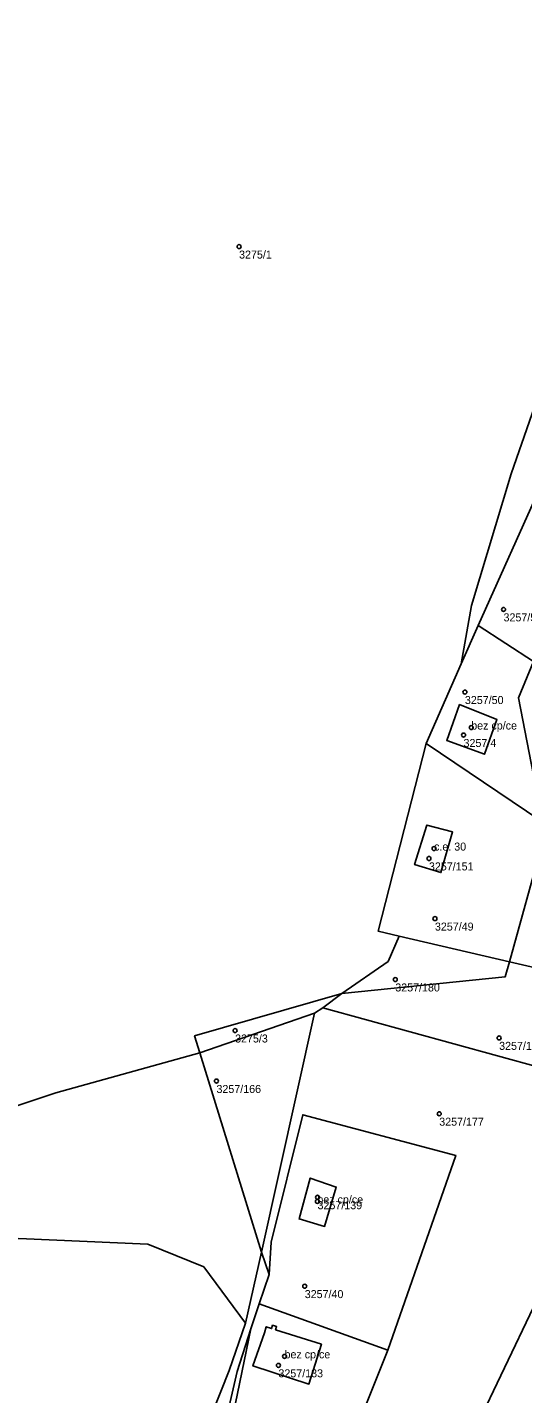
# Model space of a CAD drawing. Extents: x -878211 to -870363, y -1058464 to -1052522.
# Drawn here: x -876125.2 to -876063.3, y -1056729.3 to -1056558.5 of the extents above; entities that cross this region are included whole.
import ezdxf

# ---------------------------------------------------------------- set-up
doc = ezdxf.new("R2010")
doc.units = 0
for name, color, linetype in [('Vrstva 50', 7, 'Continuous'), ('Vrstva 51', 7, 'Continuous'), ('Vrstva 52', 7, 'Continuous')]:
    doc.layers.add(name, color=color, linetype=linetype)

msp = doc.modelspace()

# ---------------------------------------------------------------- linework, layer by layer
at = {"layer": 'Vrstva 50'}
for centre in [(-876098.72, -1056585.93994), (-876065.65, -1056631.28994), (-876070.48, -1056641.61994), (-876070.65, -1056646.98994), (-876069.69, -1056646.04994), (-876074.98, -1056662.41994), (-876074.34, -1056661.17994), (-876074.23, -1056669.93994), (-876079.19, -1056677.54994), (-876099.22, -1056683.92994), (-876066.2, -1056684.84994), (-876101.55, -1056690.23994), (-876073.69, -1056694.32994), (-876088.93, -1056705.28994), (-876088.91, -1056704.76994), (-876090.51, -1056715.87994), (-876093.8, -1056725.77994), (-876093.04, -1056724.64994)]:
    msp.add_circle(centre, 0.25, dxfattribs=at)
at = {"layer": 'Vrstva 51'}
for points in [[(-876148.16, -1056700.5), (-876121.62, -1056691.73), (-876103.64, -1056686.72), (-876104.28, -1056684.6), (-876085.87, -1056679.29), (-876080.06, -1056675.29), (-876078.71, -1056672.13), (-876081.31, -1056671.52), (-876075.34, -1056648.03), (-876070.94, -1056638.08), (-876069.67, -1056630.78), (-876064.71, -1056614.32), (-876056.8, -1056591.72), (-876042.56, -1056553.18), (-876035.37, -1056538.13), (-876027.85, -1056524.56), (-876017.07, -1056511.44), (-876044.68, -1056501.38), (-876098.73, -1056474.1), (-876103.25, -1056477.52), (-876108.02, -1056486.39), (-876113.38, -1056501.74), (-876122.52, -1056533.99), (-876125.96, -1056540.6)], [(-876042.56, -1056553.18), (-876056.8, -1056591.72), (-876064.71, -1056614.32), (-876069.67, -1056630.78), (-876070.94, -1056638.08), (-876068.81, -1056633.28), (-876060.76, -1056615.37), (-876053.64, -1056599.58), (-876052.39, -1056596.71), (-876049.88, -1056591.06), (-876048.41, -1056588.2), (-876043.14, -1056584.76), (-876040.29, -1056583.07), (-876043.26, -1056583.45), (-876046.42, -1056579.75), (-876036.33, -1056566.09), (-876027.33, -1056559.37), (-876025.32, -1056552.32)], [(-876057.84, -1056676.97), (-876064.92, -1056675.33), (-876065.44, -1056677.21), (-876085.87, -1056679.29), (-876088.26, -1056681.07), (-876055.5, -1056690.1)], [(-876030.88, -1056731.83), (-876010.97, -1056704.44), (-876010.13, -1056702.47), (-876055.5, -1056690.1), (-876088.26, -1056681.07), (-876089.29, -1056681.74), (-876095.92, -1056711.64), (-876094.94, -1056714.42), (-876094.69, -1056710.38), (-876090.76, -1056694.44), (-876071.62, -1056699.53), (-876080.1, -1056723.87), (-876085.64, -1056737.64)], [(-876069.17, -1056733.67), (-876061.91, -1056718.52), (-876055.49, -1056704.94), (-876049.98, -1056693.19), (-876021.18, -1056704.96), (-876020.86, -1056708.34), (-876027.78, -1056718.93), (-876035.95, -1056731.21)], [(-876108.71, -1056748.44), (-876099.97, -1056726.4), (-876097.92, -1056720.49), (-876103.15, -1056713.45), (-876110.12, -1056710.63), (-876126.27, -1056709.92), (-876142.37, -1056711.62), (-876162.32, -1056718.26), (-876174.86, -1056722.2), (-876191.58, -1056722.31), (-876199.78, -1056721.29), (-876212.54, -1056718.81), (-876216.57, -1056717.3), (-876255.67, -1056710.81), (-876298.64, -1056707.82), (-876323.97, -1056704.57), (-876331.67, -1056701.82), (-876328.4, -1056735.69)]]:
    msp.add_lwpolyline(points, dxfattribs=at)
for points in [[(-876068.81, -1056633.28), (-876061.89, -1056637.81), (-876059.31, -1056631.66), (-876051.13, -1056625.11), (-876039.66, -1056628.45), (-876060.76, -1056615.37)], [(-876075.34, -1056648.03), (-876060.98, -1056657.73), (-876061.1, -1056656.09), (-876063.79, -1056642.33), (-876061.89, -1056637.81), (-876068.81, -1056633.28), (-876070.94, -1056638.08)], [(-876043.28, -1056649.98), (-876061.89, -1056637.81), (-876063.79, -1056642.33), (-876061.1, -1056656.09), (-876060.98, -1056657.73), (-876051.83, -1056663.92)], [(-876066.47, -1056645.05), (-876068.03, -1056649.38), (-876072.76, -1056647.67), (-876071.14, -1056643.18)], [(-876066.47, -1056645.05), (-876071.14, -1056643.18), (-876072.76, -1056647.67), (-876068.03, -1056649.38)], [(-876060.98, -1056657.73), (-876075.34, -1056648.03), (-876081.31, -1056671.52), (-876078.71, -1056672.13), (-876064.92, -1056675.33), (-876060.79, -1056660.41)], [(-876073.47, -1056664.17), (-876076.78, -1056663.17), (-876075.26, -1056658.25), (-876072.03, -1056659.07)], [(-876073.47, -1056664.17), (-876072.03, -1056659.07), (-876075.26, -1056658.25), (-876076.78, -1056663.17)], [(-876060.98, -1056657.73), (-876060.79, -1056660.41), (-876064.92, -1056675.33), (-876057.84, -1056676.97), (-876051.83, -1056663.92)], [(-876064.92, -1056675.33), (-876078.71, -1056672.13), (-876080.06, -1056675.29), (-876085.87, -1056679.29), (-876065.44, -1056677.21)], [(-876088.26, -1056681.07), (-876085.87, -1056679.29), (-876104.28, -1056684.6), (-876103.64, -1056686.72), (-876089.29, -1056681.74)], [(-876089.29, -1056681.74), (-876103.64, -1056686.72), (-876095.92, -1056711.64)], [(-876121.62, -1056691.73), (-876148.16, -1056700.5), (-876153.47, -1056701.78), (-876173.86, -1056700.95), (-876176.72, -1056706.93), (-876187.92, -1056715.44), (-876216.57, -1056717.3), (-876212.54, -1056718.81), (-876199.78, -1056721.29), (-876191.58, -1056722.31), (-876174.86, -1056722.2), (-876162.32, -1056718.26), (-876142.37, -1056711.62), (-876126.27, -1056709.92), (-876110.12, -1056710.63), (-876103.15, -1056713.45), (-876097.92, -1056720.49), (-876095.92, -1056711.64), (-876103.64, -1056686.72)], [(-876080.1, -1056723.87), (-876071.62, -1056699.53), (-876090.76, -1056694.44), (-876094.69, -1056710.38), (-876094.94, -1056714.42), (-876096.19, -1056718.08)], [(-876088.03, -1056708.41), (-876091.22, -1056707.47), (-876089.83, -1056702.37), (-876086.58, -1056703.5)], [(-876088.03, -1056708.41), (-876086.58, -1056703.5), (-876089.83, -1056702.37), (-876091.22, -1056707.47)], [(-876094.94, -1056714.42), (-876095.92, -1056711.64), (-876097.92, -1056720.49), (-876099.97, -1056726.4), (-876108.71, -1056748.44), (-876106.32, -1056745.09), (-876100.23, -1056731.97), (-876098.98, -1056726.54), (-876097.25, -1056721.21), (-876096.19, -1056718.08)], [(-876080.1, -1056723.87), (-876096.19, -1056718.08), (-876097.25, -1056721.21), (-876101.42, -1056741.43), (-876090.17, -1056749.95), (-876085.64, -1056737.64)], [(-876035.95, -1056731.21), (-876061.91, -1056718.52), (-876069.17, -1056733.67), (-876045.29, -1056745.05)], [(-876090.17, -1056749.95), (-876101.42, -1056741.43), (-876097.25, -1056721.21), (-876098.98, -1056726.54), (-876100.23, -1056731.97), (-876106.32, -1056745.09)], [(-876094.66, -1056721.17), (-876094.53, -1056720.77), (-876094.04, -1056720.93), (-876094.16, -1056721.33), (-876088.42, -1056723.13), (-876089.99, -1056728.12), (-876097, -1056725.84), (-876095.56, -1056721.72), (-876095.33, -1056720.96)], [(-876094.66, -1056721.17), (-876095.33, -1056720.96), (-876095.56, -1056721.72), (-876097, -1056725.84), (-876089.99, -1056728.12), (-876088.42, -1056723.13), (-876094.16, -1056721.33), (-876094.04, -1056720.93), (-876094.53, -1056720.77)]]:
    msp.add_lwpolyline(points, close=True, dxfattribs=at)
at = {"layer": 'Vrstva 52'}
for points in [[(-876068.03, -1056649.38), (-876066.47, -1056645.05), (-876071.14, -1056643.18), (-876072.76, -1056647.67)], [(-876075.26, -1056658.25), (-876076.78, -1056663.17), (-876073.47, -1056664.17), (-876072.03, -1056659.07)], [(-876089.83, -1056702.37), (-876091.22, -1056707.47), (-876088.03, -1056708.41), (-876086.58, -1056703.5)], [(-876089.99, -1056728.12), (-876088.42, -1056723.13), (-876094.16, -1056721.33), (-876094.04, -1056720.93), (-876094.53, -1056720.77), (-876094.66, -1056721.17), (-876095.33, -1056720.96), (-876095.56, -1056721.72), (-876097, -1056725.84)]]:
    msp.add_lwpolyline(points, close=True, dxfattribs=at)

# ---------------------------------------------------------------- texts
at = {"layer": 'Vrstva 50'}
for s, p in [('3275/1', (-876098.72, -1056587.429)), ('3257/51', (-876065.65, -1056632.779)), ('3257/50', (-876070.48, -1056643.109)), ('bez cp/ce', (-876069.69, -1056646.3)), ('3257/4', (-876070.65, -1056648.479)), ('c.e. 30', (-876074.34, -1056661.429)), ('3257/151', (-876074.98, -1056663.909)), ('3257/49', (-876074.23, -1056671.429)), ('3257/180', (-876079.19, -1056679.039)), ('3275/3', (-876099.22, -1056685.419)), ('3257/179', (-876066.2, -1056686.339)), ('3257/166', (-876101.55, -1056691.729)), ('3257/177', (-876073.69, -1056695.819)), ('bez cp/ce', (-876088.93, -1056705.54)), ('3257/139', (-876088.91, -1056706.259)), ('3257/40', (-876090.51, -1056717.369)), ('bez cp/ce', (-876093.04, -1056724.899)), ('3257/133', (-876093.8, -1056727.269))]:
    msp.add_text(s, height=0.999996, dxfattribs=at).set_placement(p)

doc.saveas('drawing.dxf')
